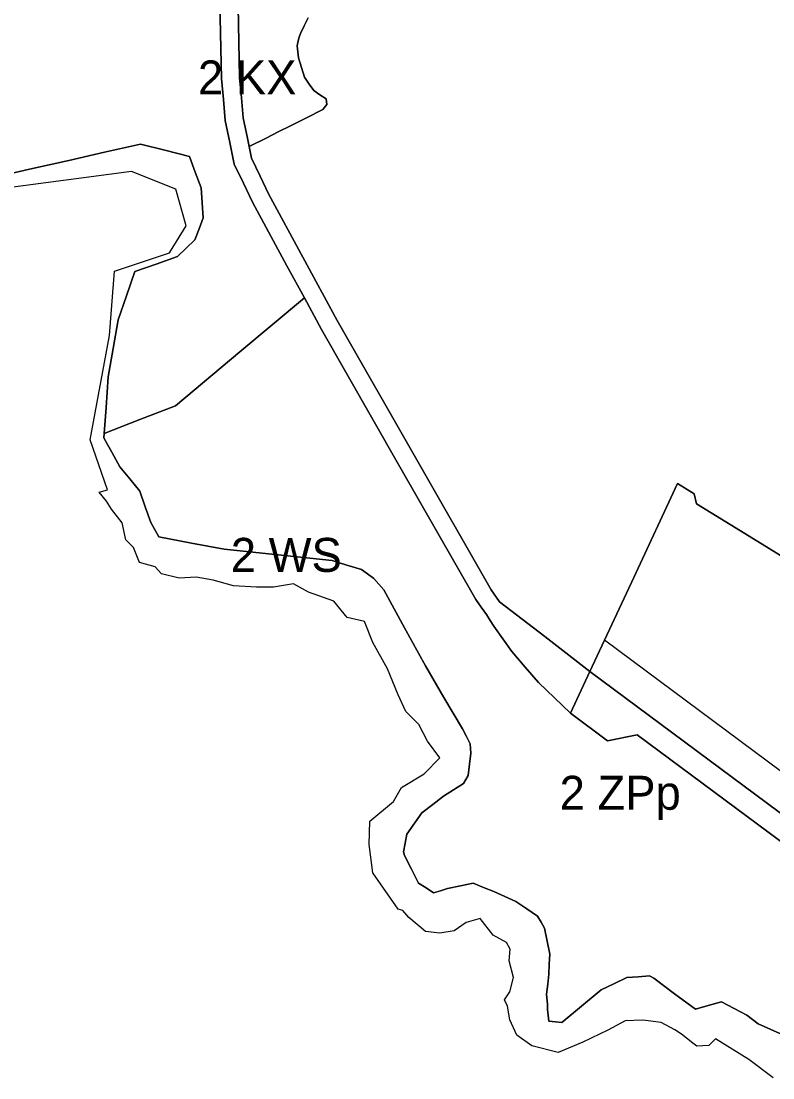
# Model space of a CAD drawing. Extents: x 7422252 to 7424226, y 5538569 to 5540380.
# Drawn here: x 7422919.5 to 7423251.5, y 5538637.3 to 5539103.9 of the extents above; entities that cross this region are included whole.
import ezdxf

# ---------------------------------------------------------------- set-up
doc = ezdxf.new("R2010")
doc.units = 0
for name, color, linetype in [('linie_rozgraniczajace', 7, 'Continuous'), ('linie_zabudowy_nieprzekraczalne', 7, 'Continuous'), ('oznaczenia_przeznaczen', 7, 'Continuous')]:
    doc.layers.add(name, color=color, linetype=linetype)

msp = doc.modelspace()

# ---------------------------------------------------------------- linework, layer by layer
at = {"layer": 'linie_rozgraniczajace'}
for points in [[(7423007.01, 5539125.74), (7423008, 5539078.57), (7423008.81, 5539069.29), (7423009.62, 5539060.01), (7423011.63, 5539050.38), (7423013.65, 5539040.74), (7423017.66, 5539032.36), (7423021.67, 5539023.98), (7423036.86, 5538995.91), (7423044.57, 5538981.66), (7423016.11, 5538957.88), (7422987.66, 5538934.09), (7422971.93, 5538927.95), (7422956.2, 5538921.82), (7422957.02, 5538933.35), (7422957.98, 5538946.78), (7422960.16, 5538959.38), (7422962.34, 5538971.99), (7422966, 5538982.65), (7422969.65, 5538993.31), (7422979.07, 5538996.63), (7422988.49, 5538999.95), (7422992.38, 5539003.62), (7422996.28, 5539007.28), (7422998.05, 5539012.19), (7422999.82, 5539017.1), (7422999.42, 5539023.71), (7422999.02, 5539030.32), (7422996.4, 5539037.24), (7422993.79, 5539044.16), (7422982.97, 5539046.86), (7422972.16, 5539049.57), (7422956.37, 5539045.99), (7422940.59, 5539042.41), (7422923.25, 5539038.48), (7422905.91, 5539034.56)], [(7423015, 5539126.07), (7423015.99, 5539079), (7423016.77, 5539070.09), (7423017.55, 5539061.18), (7423019.41, 5539052.25), (7423020.2, 5539048.48), (7423021.28, 5539043.33), (7423025.04, 5539035.47), (7423028.8, 5539027.61), (7423043.92, 5538999.67), (7423059.04, 5538971.73), (7423093.07, 5538912.25), (7423127.1, 5538852.78), (7423130.83, 5538847.49), (7423150.78, 5538832.13), (7423170.72, 5538816.78), (7423162.1, 5538798.27), (7423155.04, 5538805.03), (7423147.98, 5538811.8), (7423142.07, 5538818.66), (7423136.16, 5538825.53), (7423132.22, 5538831.11), (7423128.29, 5538836.7), (7423126.64, 5538839.29), (7423124.99, 5538841.89), (7423122.67, 5538845.18), (7423120.35, 5538848.47), (7423086.2, 5538908.16), (7423052.13, 5538967.7), (7423044.57, 5538981.66), (7423036.86, 5538995.91), (7423021.67, 5539023.98), (7423017.66, 5539032.36), (7423013.65, 5539040.74), (7423011.63, 5539050.38), (7423009.62, 5539060.01), (7423008.81, 5539069.29), (7423008, 5539078.57), (7423007.01, 5539125.74)], [(7423046.22, 5539105.36), (7423044.56, 5539101.89), (7423042.91, 5539098.41), (7423042.35, 5539096.84), (7423041.79, 5539095.26), (7423041.44, 5539093), (7423041.68, 5539090.33), (7423041.93, 5539087.67), (7423043.29, 5539083.38), (7423044.65, 5539079.1), (7423046.7, 5539076.15), (7423048.74, 5539073.21), (7423051.46, 5539071.4), (7423054.18, 5539069.59), (7423054.56, 5539067.03), (7423052.71, 5539064.89), (7423045.57, 5539061.28), (7423038.42, 5539057.67), (7423033.05, 5539054.97), (7423027.67, 5539052.26), (7423020.2, 5539048.48), (7423019.41, 5539052.25), (7423017.55, 5539061.18), (7423016.77, 5539070.09), (7423015.99, 5539079), (7423015, 5539126.07)], [(7423020.2, 5539048.48), (7423027.67, 5539052.26), (7423033.05, 5539054.97), (7423038.42, 5539057.67), (7423045.57, 5539061.28), (7423052.71, 5539064.89), (7423054.56, 5539067.03), (7423054.18, 5539069.59), (7423051.46, 5539071.4), (7423048.74, 5539073.21), (7423046.7, 5539076.15), (7423044.65, 5539079.1), (7423043.29, 5539083.38), (7423041.93, 5539087.67), (7423041.68, 5539090.33), (7423041.44, 5539093), (7423041.79, 5539095.26), (7423042.35, 5539096.84), (7423042.91, 5539098.41), (7423044.56, 5539101.89), (7423046.22, 5539105.36)], [(7422940.59, 5539042.41), (7422956.37, 5539045.99), (7422972.16, 5539049.57), (7422982.97, 5539046.86), (7422993.79, 5539044.16), (7422996.4, 5539037.24), (7422999.02, 5539030.32), (7422999.42, 5539023.71), (7422999.82, 5539017.1), (7422998.05, 5539012.19), (7422996.28, 5539007.28), (7422992.38, 5539003.62), (7422988.49, 5538999.95), (7422979.07, 5538996.63), (7422969.65, 5538993.31), (7422966, 5538982.65), (7422962.34, 5538971.99), (7422960.16, 5538959.38), (7422957.98, 5538946.78), (7422957.02, 5538933.35), (7422956.2, 5538921.82), (7422956.07, 5538919.91), (7422957.65, 5538917.01), (7422959.56, 5538913.51), (7422963.05, 5538907.12), (7422967.46, 5538901.74), (7422971.87, 5538896.36), (7422974.32, 5538889.42), (7422976.76, 5538882.48), (7422980.24, 5538876.2), (7422994.72, 5538873.44), (7423009.2, 5538870.68), (7423033.01, 5538868.19), (7423056.82, 5538865.7), (7423063.31, 5538863.73), (7423069.8, 5538861.76), (7423072.52, 5538859.79), (7423075.24, 5538857.82), (7423077.44, 5538855.31), (7423079.63, 5538852.8), (7423088.82, 5538836.03), (7423098.01, 5538819.25), (7423106.2, 5538805.32), (7423114.39, 5538791.4), (7423116.13, 5538788.07), (7423117.86, 5538784.75), (7423118.05, 5538780.74), (7423117.48, 5538775.74), (7423116.92, 5538770.75), (7423115.9, 5538768.97), (7423114.87, 5538767.2), (7423110.47, 5538764.46), (7423106.07, 5538761.72), (7423101.28, 5538757.98), (7423096.5, 5538754.25), (7423089.86, 5538744.83), (7423089.09, 5538740.96), (7423088.32, 5538737.09), (7423088.75, 5538735.49), (7423091.89, 5538729.39), (7423095.04, 5538723.3), (7423098.35, 5538721.14), (7423101.65, 5538718.97), (7423104.73, 5538719.94), (7423107.81, 5538720.91), (7423113.48, 5538722.06), (7423119.15, 5538723.21), (7423123.69, 5538721.39), (7423128.23, 5538719.58), (7423133.1, 5538717.34), (7423137.97, 5538715.1), (7423142.76, 5538711.9), (7423147.56, 5538708.7), (7423149.11, 5538706.08), (7423150.66, 5538703.46), (7423151.82, 5538697.67), (7423152.99, 5538691.88), (7423152.74, 5538687.51), (7423152.49, 5538683.13), (7423152.03, 5538678.68), (7423151.57, 5538674.23), (7423151.96, 5538669.64), (7423151.97, 5538667.47), (7423152.29, 5538664.93), (7423152.61, 5538662.39), (7423155.42, 5538662.03), (7423158.23, 5538661.67), (7423166.94, 5538668.9), (7423175.65, 5538676.12), (7423181.32, 5538678.84), (7423186.99, 5538681.57), (7423191.99, 5538681.93), (7423196.99, 5538682.3), (7423198.92, 5538681.36), (7423208.09, 5538674.46), (7423217.26, 5538667.56), (7423222.92, 5538669.25), (7423228.81, 5538670.82), (7423234.4, 5538667.89), (7423240, 5538664.95)], [(7423283.95, 5538850.42), (7423272.25, 5538857.45), (7423260.55, 5538864.49), (7423239.13, 5538877.64), (7423217.72, 5538890.79), (7423216.7, 5538895.17), (7423209.33, 5538899.71), (7423190.02, 5538858.24), (7423170.72, 5538816.78), (7423150.78, 5538832.13), (7423130.83, 5538847.49), (7423127.1, 5538852.78), (7423093.07, 5538912.25), (7423059.04, 5538971.73), (7423043.92, 5538999.67), (7423028.8, 5539027.61), (7423025.04, 5539035.47), (7423021.28, 5539043.33), (7423020.2, 5539048.48)], [(7422905.91, 5539034.56), (7422923.25, 5539038.48), (7422940.59, 5539042.41)], [(7423073.13, 5538740.41), (7423073.43, 5538750.69), (7423083.98, 5538759.32), (7423087.42, 5538765.49), (7423097.42, 5538771.48), (7423104.34, 5538778.6), (7423098.9, 5538785.91), (7423095.07, 5538793.33), (7423089.34, 5538799.05), (7423086.02, 5538806.46), (7423081.28, 5538817.86), (7423074.77, 5538829.6), (7423071.11, 5538838.82), (7423063.55, 5538840.51), (7423057.65, 5538847.73), (7423046.4, 5538851.76), (7423039.73, 5538855.49), (7423031.01, 5538854), (7423023.44, 5538853.9), (7423013.21, 5538854.53), (7423004.35, 5538857.1), (7422996.81, 5538858.33), (7422989.31, 5538857.94), (7422981.44, 5538859.9), (7422978.75, 5538862.91), (7422971.79, 5538864.85), (7422969.13, 5538871.43), (7422965.78, 5538874.85), (7422964.05, 5538882.39), (7422959.41, 5538888.43), (7422957.13, 5538891.99), (7422953.93, 5538895.85), (7422957.57, 5538896.92), (7422950.02, 5538919.02), (7422958.47, 5538965.04), (7422960.69, 5538993.44), (7422985, 5539001.54), (7422992.34, 5539013.58), (7422987.77, 5539029.76), (7422968.29, 5539037.5), (7422900.2, 5539028.48)], [(7422956.07, 5538919.91), (7422956.2, 5538921.82), (7422971.93, 5538927.95), (7422987.66, 5538934.09), (7423016.11, 5538957.88), (7423044.57, 5538981.66), (7423052.13, 5538967.7), (7423086.2, 5538908.16), (7423120.35, 5538848.47), (7423122.67, 5538845.18), (7423124.99, 5538841.89), (7423126.64, 5538839.29), (7423128.29, 5538836.7), (7423132.22, 5538831.11), (7423136.16, 5538825.53), (7423142.07, 5538818.66), (7423147.98, 5538811.8), (7423155.04, 5538805.03), (7423162.1, 5538798.27), (7423178.49, 5538786.09), (7423191.56, 5538788.83), (7423225.24, 5538763.79), (7423258.92, 5538738.75)], [(7423191.99, 5538681.93), (7423186.99, 5538681.57), (7423181.32, 5538678.84), (7423175.65, 5538676.12), (7423166.94, 5538668.9), (7423158.23, 5538661.67), (7423155.42, 5538662.03), (7423152.61, 5538662.39), (7423152.29, 5538664.93), (7423151.97, 5538667.47), (7423151.96, 5538669.64), (7423151.57, 5538674.23), (7423152.03, 5538678.68), (7423152.49, 5538683.13), (7423152.74, 5538687.51), (7423152.99, 5538691.88), (7423151.82, 5538697.67), (7423150.66, 5538703.46), (7423149.11, 5538706.08), (7423147.56, 5538708.7), (7423142.76, 5538711.9), (7423137.97, 5538715.1), (7423133.1, 5538717.34), (7423128.23, 5538719.58), (7423123.69, 5538721.39), (7423119.15, 5538723.21), (7423113.48, 5538722.06), (7423107.81, 5538720.91), (7423104.73, 5538719.94), (7423101.65, 5538718.97), (7423098.35, 5538721.14), (7423095.04, 5538723.3), (7423091.89, 5538729.39), (7423088.75, 5538735.49), (7423088.32, 5538737.09), (7423089.09, 5538740.96), (7423089.86, 5538744.83), (7423096.5, 5538754.25), (7423101.28, 5538757.98), (7423106.07, 5538761.72), (7423110.47, 5538764.46), (7423114.87, 5538767.2), (7423115.9, 5538768.97), (7423116.92, 5538770.75), (7423117.48, 5538775.74), (7423118.05, 5538780.74), (7423117.86, 5538784.75), (7423116.13, 5538788.07), (7423114.39, 5538791.4), (7423106.2, 5538805.32), (7423098.01, 5538819.25), (7423088.82, 5538836.03), (7423079.63, 5538852.8), (7423077.44, 5538855.31), (7423075.24, 5538857.82), (7423072.52, 5538859.79), (7423069.8, 5538861.76), (7423063.31, 5538863.73), (7423056.82, 5538865.7), (7423033.01, 5538868.19), (7423009.2, 5538870.68), (7422994.72, 5538873.44), (7422980.24, 5538876.2), (7422976.76, 5538882.48), (7422974.32, 5538889.42), (7422971.87, 5538896.36), (7422967.46, 5538901.74), (7422963.05, 5538907.12), (7422959.56, 5538913.51), (7422957.65, 5538917.01), (7422956.07, 5538919.91)], [(7423264.59, 5538747), (7423217.65, 5538781.89), (7423170.72, 5538816.78), (7423190.02, 5538858.24), (7423209.33, 5538899.71), (7423216.7, 5538895.17), (7423217.72, 5538890.79), (7423239.13, 5538877.64), (7423260.55, 5538864.49)], [(7423258.92, 5538738.75), (7423225.24, 5538763.79), (7423191.56, 5538788.83), (7423178.49, 5538786.09), (7423162.1, 5538798.27), (7423170.72, 5538816.78), (7423217.65, 5538781.89), (7423264.59, 5538747)], [(7423251.56, 5538637.29), (7423240.85, 5538645.34), (7423226.21, 5538654.59), (7423223.18, 5538651.54), (7423217.96, 5538651.27), (7423216.21, 5538652.6), (7423211.11, 5538656.57), (7423208.18, 5538658.52), (7423202.19, 5538661.74), (7423194, 5538662.76), (7423186.27, 5538662.41), (7423178.61, 5538658.4), (7423167.62, 5538653.07), (7423156.64, 5538648.47), (7423145.09, 5538651.47), (7423138.41, 5538656.08), (7423135.38, 5538662.89), (7423134.24, 5538669.02), (7423133.01, 5538671.73), (7423135.29, 5538675.21), (7423136.9, 5538681.54), (7423135, 5538689.01), (7423135.4, 5538694.11), (7423133.92, 5538697.06), (7423127.89, 5538700.24), (7423122.19, 5538707.6), (7423116.08, 5538705.9), (7423110.78, 5538702.15), (7423104.37, 5538701.13), (7423098.02, 5538701.85), (7423090.68, 5538708.09), (7423088.05, 5538711.21), (7423086.01, 5538711.82), (7423074.89, 5538727.85), (7423073.13, 5538740.41)], [(7423254.49, 5538656.9), (7423244.95, 5538661.13), (7423242.47, 5538663.04), (7423240, 5538664.95), (7423234.4, 5538667.89), (7423228.81, 5538670.82), (7423222.92, 5538669.25), (7423217.26, 5538667.56), (7423208.09, 5538674.46), (7423198.92, 5538681.36), (7423196.99, 5538682.3), (7423191.99, 5538681.93)], [(7423240, 5538664.95), (7423242.47, 5538663.04), (7423244.95, 5538661.13), (7423254.49, 5538656.9)]]:
    msp.add_lwpolyline(points, dxfattribs=at)
at = {"layer": 'linie_zabudowy_nieprzekraczalne'}
msp.add_lwpolyline([(7423177.18, 5538830.67), (7423177.18, 5538830.67), (7423273.08, 5538759.37)], dxfattribs=at)

# ---------------------------------------------------------------- texts
at = {"layer": 'oznaczenia_przeznaczen'}
for s, p in [('2 KX', (7422997.6, 5539071.55)), ('2 WS', (7423012.08, 5538860.72)), ('2 ZPp', (7423157.3, 5538755.68))]:
    msp.add_text(s, height=15, dxfattribs=at).set_placement(p)

doc.saveas('drawing.dxf')
